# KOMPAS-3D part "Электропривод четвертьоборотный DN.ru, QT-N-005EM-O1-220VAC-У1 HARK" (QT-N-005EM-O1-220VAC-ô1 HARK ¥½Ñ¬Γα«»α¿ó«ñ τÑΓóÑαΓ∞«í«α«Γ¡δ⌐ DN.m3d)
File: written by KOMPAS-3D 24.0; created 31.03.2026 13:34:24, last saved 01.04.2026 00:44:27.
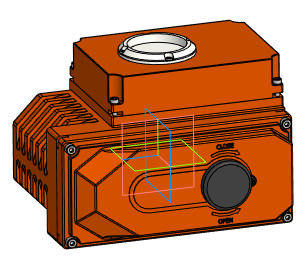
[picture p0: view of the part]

Document properties: Автор: DN.RU; Полное имя файла: D:\PROJECT CAD\DN.RU\...195\Исходники\220В\QT-N-005EM-O1-220VAC-У1 HARK Электропривод четвертьоборотный DN.ru\QT-N-005EM-O1-220VAC-У1 HARK Электропривод четвертьоборотный DN.m3d

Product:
- Body: Твердое тело1  | qty 1
    Масса: 13.496569
- Part/product: Электропривод четвертьоборотный DN.ru  | designation QT-N-005EM-O1-220VAC-У1 HARK
    Масса: 3.6
    Раздел спецификации: Прочие изделия
    Комментарий: D300-14478
    Примечание: D300-14477
    additional columns: Сталь

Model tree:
1. Твердое тело1  (labels: Твердое тело1)

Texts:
  QT-N-005EM-O1-220VAC-У1 HARK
